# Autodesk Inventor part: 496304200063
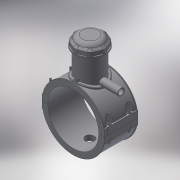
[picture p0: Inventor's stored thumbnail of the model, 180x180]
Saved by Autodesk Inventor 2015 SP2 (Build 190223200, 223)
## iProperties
Created: 2017-07
Part Number: 496304200063
Material: Generic
Description: PLASSON TAPPING SADDLE 200x63
Document SubType Name: Modeling
Designer: KIM
Mass: 1401.21 g
Surface Area: 3381.08 cm^2
Volume: 1401.21 cm^3
Density: 1 g/cm^3
Appearance: Default
Author: KIM
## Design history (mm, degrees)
derived "496304.ipt"
feature "Solid1::496304.ipt"
feature "Solid2::496304.ipt"
feature "Solid4::496304.ipt"
feature "Solid5::496304.ipt"
tag "TaggingFeature1" dims "d2" = 262.6
body "Solid1"
body "Solid2"
other parameters: "d4" = 176, "d5" = 0, "d6" = 0.1, "d8" = 0, "d19" = 6, "d20" = 6, "d21" = 105.6, "d23" = 0, "d24" = 52.8, "d26" = 0, "d29" = 3, "d30" = 66.66667, "d31" = 6, "d32" = 0, "d33" = 0, "d34" = 0.6, "d40" = 118.56, "d43" = 0, "d45" = 0, "d47" = 219.6, "d70" = 15, "d72" = 0, "d73" = 6, "d75" = 5, "d76" = 0, "d79" = 15, "d80" = 70.4, "d82" = 5 deg, "d84" = 4, "d85" = 14, "d86" = 0, "d87" = 3, "d88" = 0, "d89" = 1, "d90" = 1, "d91" = 140.8, "d92" = 0, "d93" = 0.5, "d94" = 105.26316, "d96" = 232.56, "d97" = 3.52, "d98" = 0, "d102" = 2, "d120" = 140 deg, "d121" = 24.228, "d122" = 20 deg, "d123" = 456, "d124" = 136.8, "d126" = 0, "d143" = 206, "d145" = 21.53846, "d149" = 3, "d150" = 23.69231, "d153" = 176, "d154" = 0, "d156" = 114, "d157" = 160 deg, "d159" = 5.6, "d161" = 3, "d162" = 105.6, "d163" = 0, "d168" = 111.21951, "d170" = 3, "d172" = 0, "d173" = 1, "d176" = 20 deg, "d177" = 14, "d178" = 28, "d180" = 0, "d183" = 11.2, "d184" = 11.2, "d185" = 57.2, "d186" = 57.2, "d187" = 114, "d188" = 8.4, "d189" = 14, "d190" = 0, "d191" = 171, "d193" = 5.6, "d194" = 6.16, "d195" = 90 deg, "d197" = 0, "d199" = 0, "d200" = 14, "d202" = 0, "d203" = 177, "d204" = 76, "d205" = 56, "d206" = 68, "d207" = 132.75, "d208" = 138.06, "d209" = 164.61, "d210" = 68.8, "d212" = 64, "d213" = 29.25, "d216" = 0, "d219" = 4, "d224" = 0, "d230" = 4, "d233" = 6, "d236" = 101, "d237" = 52.8, "d238" = 6.02433, "d240" = 52.8, "d241" = 52.8, "d242" = 52.8, "d243" = 6, "d244" = 52.8, "d245" = 52.8, "d246" = 52.8, "d247" = 6, "d248" = 6, "d249" = 6, "d251" = 52.8, "d253" = 6, "d254" = 6, "d255" = 52.8, "d256" = 6, "d257" = 164, "d258" = 175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
